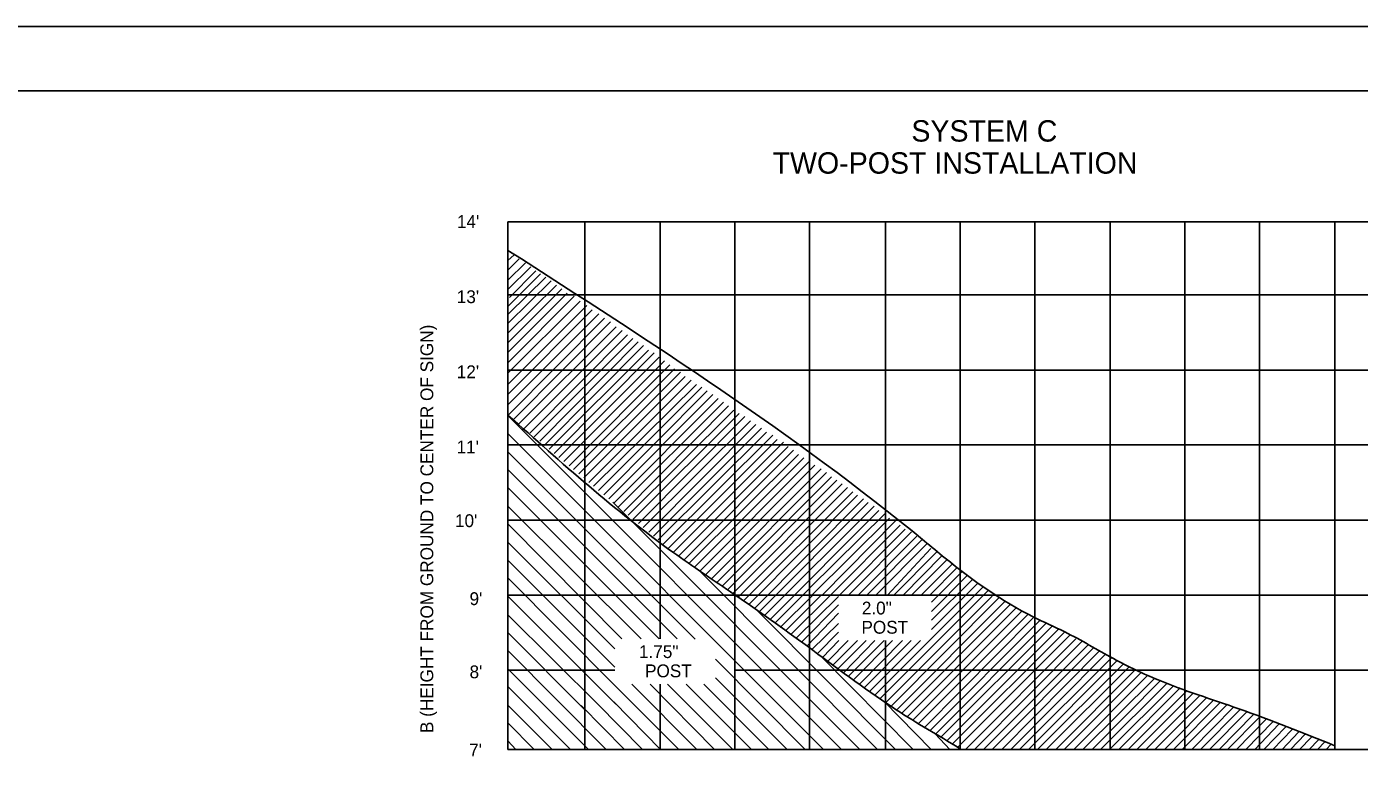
# Model space of a CAD drawing. Extents: x 644358 to 648627, y 294594 to 295782.
# Drawn here: x 647140.2 to 647452.3, y 295609 to 295781.6 of the extents above; entities that cross this region are included whole.
import ezdxf

# ---------------------------------------------------------------- set-up
doc = ezdxf.new("R2010")
doc.units = 0
for name, color, linetype in [('1', 7, 'Continuous'), ('10', 7, 'Continuous'), ('2', 7, 'Continuous'), ('4', 7, 'Continuous'), ('PLT-BNDY', 7, 'Continuous')]:
    doc.layers.add(name, color=color, linetype=linetype)

msp = doc.modelspace()

# ---------------------------------------------------------------- linework, layer by layer
at = {"layer": '1'}
msp.add_line((646921.31, 295766.63), (647707.31, 295766.63), dxfattribs=at)
at = {"layer": '10'}
for p, q in [((647252.91, 295726.91), (647254.39, 295728.25)), ((647252.91, 295724.66), (647255.53, 295727.29)), ((647252.91, 295722.29), (647257.03, 295726.41)), ((647252.91, 295720.16), (647258.28, 295725.41)), ((647253.03, 295716.29), (647260.53, 295723.79)), ((647253.03, 295714.41), (647261.78, 295723.04)), ((647253.28, 295718.29), (647259.41, 295724.54)), ((647252.91, 295712.16), (647263.03, 295722.16)), ((647252.91, 295709.91), (647264.28, 295721.16)), ((647253.03, 295707.79), (647265.53, 295720.29)), ((647252.91, 295705.41), (647266.78, 295719.29)), ((647252.91, 295700.54), (647269.78, 295717.41)), ((647252.91, 295697.91), (647271.41, 295716.41)), ((647253.03, 295703.16), (647268.41, 295718.54)), ((647252.91, 295695.54), (647272.66, 295715.41)), ((647252.91, 295693.16), (647274.16, 295714.41)), ((647252.91, 295690.66), (647275.53, 295713.41)), ((647254.28, 295689.79), (647276.91, 295712.54)), ((647255.41, 295688.66), (647278.28, 295711.41)), ((647256.66, 295687.54), (647279.66, 295710.54)), ((647258.03, 295686.54), (647280.91, 295709.54)), ((647259.03, 295685.66), (647282.16, 295708.66)), ((647260.41, 295684.66), (647283.41, 295707.91)), ((647261.41, 295683.66), (647284.66, 295707.04)), ((647262.53, 295682.79), (647285.78, 295705.91)), ((647263.75, 295681.76), (647287.16, 295705.29)), ((647264.84, 295680.85), (647288.28, 295704.29)), ((647266, 295679.88), (647289.53, 295703.41)), ((647267.23, 295678.86), (647290.78, 295702.54)), ((647268.25, 295678.01), (647291.91, 295701.54)), ((647269.48, 295676.99), (647293.28, 295700.79)), ((647270.66, 295676.04), (647294.41, 295699.79)), ((647271.87, 295675), (647295.78, 295698.91)), ((647272.96, 295674.1), (647297.03, 295697.91)), ((647274.12, 295673.13), (647298.28, 295697.29)), ((647275.35, 295672.11), (647299.53, 295696.41)), ((647276.51, 295671.15), (647300.91, 295695.54)), ((647277.67, 295670.18), (647302.16, 295694.66)), ((647278.77, 295669.27), (647303.41, 295693.79)), ((647280.06, 295668.2), (647304.53, 295692.91)), ((647281.09, 295667.34), (647305.78, 295691.91)), ((647252.91, 295690.66), (647331.03, 295612.54)), ((647282.25, 295666.38), (647307.03, 295691.16)), ((647283.47, 295665.36), (647308.41, 295690.41)), ((647284.57, 295664.45), (647309.66, 295689.41)), ((647285.86, 295663.37), (647310.91, 295688.54)), ((647326.78, 295612.54), (647252.91, 295686.41)), ((647286.96, 295662.46), (647312.28, 295687.66)), ((647288.05, 295661.56), (647313.41, 295686.79)), ((647289.28, 295660.54), (647314.91, 295686.04)), ((647296.71, 295638.36), (647252.91, 295682.16)), ((647290.41, 295659.54), (647315.91, 295685.04)), ((647291.66, 295658.66), (647317.41, 295684.41)), ((647292.91, 295657.79), (647318.53, 295683.41)), ((647294.16, 295656.91), (647319.78, 295682.54)), ((647295.32, 295656.08), (647320.91, 295681.54)), ((647296.58, 295655.21), (647322.16, 295680.79)), ((647297.91, 295654.29), (647323.66, 295680.16)), ((647299.16, 295653.41), (647324.78, 295679.04)), ((647292.56, 295638.38), (647252.91, 295678.04)), ((647300.57, 295652.45), (647326.28, 295678.16)), ((647301.84, 295651.6), (647327.53, 295677.29)), ((647303.08, 295650.71), (647328.66, 295676.29)), ((647288.3, 295638.4), (647252.91, 295673.79)), ((647304.28, 295649.91), (647329.91, 295675.54)), ((647305.53, 295649.04), (647331.16, 295674.66)), ((647306.78, 295648.16), (647332.41, 295673.79)), ((647308.03, 295647.29), (647333.66, 295672.79)), ((647335.28, 295612.54), (647277.46, 295670.36)), ((647309.28, 295646.41), (647334.78, 295672.04)), ((647310.53, 295645.41), (647336.16, 295671.16)), ((647311.66, 295644.66), (647337.28, 295670.29)), ((647284.06, 295638.41), (647252.91, 295669.41)), ((647312.91, 295643.79), (647338.66, 295669.41)), ((647314.28, 295642.91), (647339.78, 295668.41)), ((647323.53, 295650.23), (647341.28, 295667.79)), ((647324.07, 295648.66), (647342.28, 295666.66)), ((647279.61, 295638.43), (647252.91, 295665.29)), ((647326.5, 295648.66), (647343.66, 295666.04)), ((647328.41, 295648.66), (647344.78, 295665.04)), ((647330.53, 295648.66), (647345.91, 295664.04)), ((647332.66, 295648.66), (647347.41, 295663.41)), ((647277.95, 295636.1), (647252.91, 295661.04)), ((647334.91, 295648.66), (647348.66, 295662.41)), ((647336.91, 295648.66), (647350.03, 295661.79)), ((647339.03, 295648.66), (647350.91, 295660.54)), ((647341.78, 295648.66), (647351.91, 295659.54)), ((647343.28, 295648.66), (647353.28, 295658.66)), ((647345.41, 295648.66), (647354.53, 295657.79)), ((647277.95, 295631.75), (647252.91, 295656.79)), ((647339.41, 295612.54), (647297.61, 295654.46)), ((647347.41, 295648.66), (647355.66, 295656.91)), ((647349.66, 295648.66), (647356.91, 295655.91)), ((647351.66, 295648.66), (647358.03, 295655.04)), ((647352.11, 295646.99), (647359.28, 295654.16)), ((647277.95, 295627.51), (647252.91, 295652.66)), ((647352.11, 295644.83), (647360.53, 295653.29)), ((647352.11, 295642.74), (647361.66, 295652.29)), ((647352.11, 295640.62), (647362.91, 295651.41)), ((647278.16, 295623.16), (647252.91, 295648.41)), ((647315.41, 295642.04), (647323.53, 295650.16)), ((647316.66, 295641.04), (647324.28, 295648.66)), ((647317.91, 295640.29), (647326.28, 295648.66)), ((647319.16, 295639.41), (647328.41, 295648.66)), ((647320.41, 295638.54), (647330.34, 295648.3)), ((647340.03, 295624.41), (647365.41, 295649.79)), ((647341.41, 295623.54), (647366.28, 295648.41)), ((647342.66, 295622.66), (647367.91, 295648.04)), ((647352.11, 295638.49), (647364.16, 295650.54)), ((647343.66, 295612.54), (647311.41, 295644.91)), ((647321.66, 295637.66), (647330.34, 295646.35)), ((647343.78, 295621.66), (647369.41, 295647.29)), ((647345.03, 295620.91), (647370.53, 295646.41)), ((647346.34, 295620.1), (647371.91, 295645.66)), ((647347.63, 295619.27), (647373.34, 295644.98)), ((647274.28, 295622.79), (647252.91, 295644.04)), ((647322.91, 295636.66), (647330.34, 295644.44)), ((647324.03, 295635.91), (647330.34, 295641.99)), ((647348.91, 295618.41), (647374.7, 295644.21)), ((647350.34, 295617.6), (647375.91, 295643.29)), ((647351.66, 295616.91), (647377.53, 295642.79)), ((647352.91, 295616.04), (647378.91, 295642.04)), ((647271.03, 295621.66), (647252.91, 295639.91)), ((647325.28, 295634.91), (647330.34, 295639.97)), ((647338.91, 295625.29), (647352.11, 295638.49)), ((647354.28, 295615.41), (647380.28, 295641.29)), ((647355.72, 295614.6), (647381.86, 295640.74)), ((647356.96, 295613.85), (647383.16, 295639.91)), ((647358.28, 295613.04), (647384.58, 295639.34)), ((647360.03, 295612.54), (647385.91, 295638.41)), ((647275.91, 295612.54), (647252.91, 295635.66)), ((647326.53, 295634.04), (647330.41, 295637.98)), ((647327.91, 295633.29), (647332.6, 295637.98)), ((647329.03, 295632.29), (647334.72, 295637.98)), ((647330.28, 295631.54), (647336.8, 295637.98)), ((647331.53, 295630.54), (647338.79, 295637.98)), ((647332.66, 295629.66), (647340.97, 295637.98)), ((647333.91, 295628.91), (647342.97, 295637.98)), ((647335.28, 295627.91), (647345.3, 295637.98)), ((647336.41, 295627.04), (647347.35, 295637.98)), ((647337.66, 295626.16), (647349.47, 295637.98)), ((647362.16, 295612.54), (647387.28, 295637.79)), ((647364.28, 295612.54), (647388.66, 295636.91)), ((647366.28, 295612.54), (647390.03, 295636.29)), ((647368.53, 295612.54), (647391.28, 295635.41)), ((647322.53, 295612.54), (647301.54, 295633.65)), ((647347.78, 295612.54), (647326.03, 295634.54)), ((647370.66, 295612.54), (647392.66, 295634.66)), ((647372.65, 295612.54), (647394.25, 295634)), ((647374.78, 295612.54), (647395.41, 295633.16)), ((647376.9, 295612.54), (647397.03, 295632.54)), ((647271.78, 295612.54), (647252.91, 295631.41)), ((647318.28, 295612.54), (647301.54, 295629.28)), ((647378.9, 295612.54), (647398.41, 295631.91)), ((647381.16, 295612.54), (647399.79, 295631.17)), ((647383.16, 295612.54), (647401.14, 295630.52)), ((647385.41, 295612.54), (647402.69, 295629.82)), ((647387.53, 295612.54), (647404.26, 295629.15)), ((647267.53, 295612.54), (647252.91, 295627.29)), ((647282.41, 295623.04), (647277.95, 295627.51)), ((647297.16, 295612.54), (647281.88, 295627.81)), ((647301.28, 295612.54), (647286.22, 295627.81)), ((647305.53, 295612.54), (647290.25, 295627.81)), ((647309.91, 295612.54), (647294.63, 295627.81)), ((647314.03, 295612.54), (647298.75, 295627.81)), ((647389.66, 295612.54), (647405.66, 295628.66)), ((647391.65, 295612.54), (647407.28, 295628.04)), ((647393.77, 295612.54), (647408.78, 295627.41)), ((647395.91, 295612.54), (647410.28, 295626.91)), ((647398.16, 295612.54), (647411.78, 295626.16)), ((647263.28, 295612.54), (647252.91, 295622.91)), ((647280.16, 295612.54), (647270.03, 295622.79)), ((647284.41, 295612.54), (647273.78, 295623.29)), ((647288.66, 295612.54), (647277.66, 295623.66)), ((647292.91, 295612.54), (647282.16, 295623.29)), ((647352.03, 295612.54), (647340.91, 295623.79)), ((647400.16, 295612.54), (647413.42, 295625.8)), ((647402.28, 295612.54), (647415, 295625.25)), ((647404.41, 295612.54), (647416.58, 295624.71)), ((647406.66, 295612.54), (647418.15, 295624.16)), ((647408.78, 295612.54), (647419.72, 295623.61)), ((647410.78, 295612.54), (647421.29, 295623.05)), ((647413.03, 295612.54), (647422.84, 295622.48)), ((647415.03, 295612.54), (647424.39, 295621.9)), ((647417.16, 295612.54), (647425.93, 295621.32)), ((647419.41, 295612.54), (647427.47, 295620.73)), ((647421.41, 295612.54), (647428.92, 295620.18)), ((647259.03, 295612.54), (647252.91, 295618.79)), ((647423.53, 295612.54), (647430.45, 295619.6)), ((647425.66, 295612.54), (647431.99, 295619.01)), ((647427.78, 295612.54), (647433.44, 295618.46)), ((647429.91, 295612.54), (647435.03, 295617.79)), ((647432.03, 295612.54), (647436.53, 295617.16)), ((647434.16, 295612.54), (647438.03, 295616.54)), ((647254.78, 295612.54), (647252.91, 295614.54)), ((647356.41, 295612.54), (647352.91, 295616.16)), ((647436.14, 295612.54), (647439.59, 295616.11)), ((647438.28, 295612.54), (647441.03, 295615.41)), ((647440.53, 295612.54), (647442.66, 295614.79)), ((647442.48, 295612.54), (647444.21, 295614.32)), ((647444.52, 295612.54), (647445.68, 295613.75))]:
    msp.add_line(p, q, dxfattribs=at)
at = {"layer": '2'}
for p, q in [((647252.91, 295612.54), (647252.91, 295735.97)), ((647487.16, 295735.97), (647252.91, 295735.97)), ((647270.91, 295612.54), (647270.91, 295735.97)), ((647288.53, 295735.97), (647288.53, 295638.4)), ((647306.03, 295735.97), (647306.03, 295631.04)), ((647323.53, 295612.54), (647323.53, 295735.97)), ((647341.28, 295648.66), (647341.28, 295735.97)), ((647358.78, 295612.54), (647358.78, 295735.97)), ((647376.28, 295735.97), (647376.28, 295612.41)), ((647393.91, 295612.54), (647393.91, 295735.97)), ((647411.41, 295612.66), (647411.41, 295735.97)), ((647428.91, 295612.54), (647428.91, 295735.97)), ((647446.53, 295612.54), (647446.53, 295735.97)), ((647487.16, 295718.91), (647252.91, 295718.91)), ((647487.16, 295701.29), (647252.91, 295701.29)), ((647487.16, 295683.79), (647252.91, 295683.79)), ((647487.16, 295666.16), (647252.91, 295666.16)), ((647252.91, 295648.66), (647487.16, 295648.66)), ((647341.28, 295612.54), (647341.28, 295637.98)), ((647252.91, 295631.04), (647277.95, 295631.04)), ((647306.03, 295631.04), (647487.16, 295631.04)), ((647306.03, 295631.04), (647306.03, 295624.41)), ((647288.53, 295627.81), (647288.53, 295612.54)), ((647306.03, 295624.91), (647306.03, 295612.54)), ((647487.16, 295612.54), (647252.91, 295612.54))]:
    msp.add_line(p, q, dxfattribs=at)
at = {"layer": '4'}
msp.add_line((647357.66, 295613.41), (647359.04, 295612.54), dxfattribs=at)
for points in [[(647446.53, 295613.41), (647424.03, 295622.04), (647405.16, 295628.79), (647394.66, 295633.79), (647383.28, 295640.04), (647375.91, 295643.54), (647355.28, 295657.29), (647350.41, 295661.29), (647252.91, 295729.29)], [(647357.66, 295613.41), (647342.91, 295622.41), (647323.03, 295636.66), (647305.91, 295648.79), (647291.53, 295658.66), (647252.91, 295690.77)]]:
    msp.add_spline(points, degree=3, dxfattribs=at)
at = {"layer": 'PLT-BNDY'}
msp.add_lwpolyline([(646881.31, 295781.63), (647722.31, 295781.63), (647722.31, 295187.63), (646881.31, 295187.63)], close=True, dxfattribs=at)

# ---------------------------------------------------------------- texts
at = {"layer": '4'}
for s, height, p in [('SYSTEM C', 5, (647347.37, 295754.74)), ('TWO-POST INSTALLATION', 5, (647314.87, 295747.24)), ("14'", 3, (647240.96, 295734.53)), ('2.0"', 3, (647335.77, 295644.11)), ('POST', 3, (647335.68, 295639.61)), ('1.75"', 3, (647283.59, 295633.91)), ('POST', 3, (647285.01, 295629.41))]:
    msp.add_text(s, height=height, dxfattribs=at).set_placement(p)
for s, height, rotation, p in [("13'", 3, 360, (647240.93, 295716.95)), (' B (HEIGHT FROM GROUND TO CENTER OF SIGN)', 3.005, 90, (647235.42, 295615.25)), ("12'", 3, 360, (647240.93, 295699.39)), ("11'", 3, 360, (647240.87, 295681.79)), ("10'", 3, 360, (647240.51, 295664.55)), ("9'", 3, 360, (647243.92, 295646.3)), ("8'", 3, 360, (647243.92, 295629.18)), ("7'", 3, 360, (647243.82, 295610.88))]:
    msp.add_text(s, height=height, rotation=rotation, dxfattribs=at).set_placement(p)

doc.saveas('drawing.dxf')
